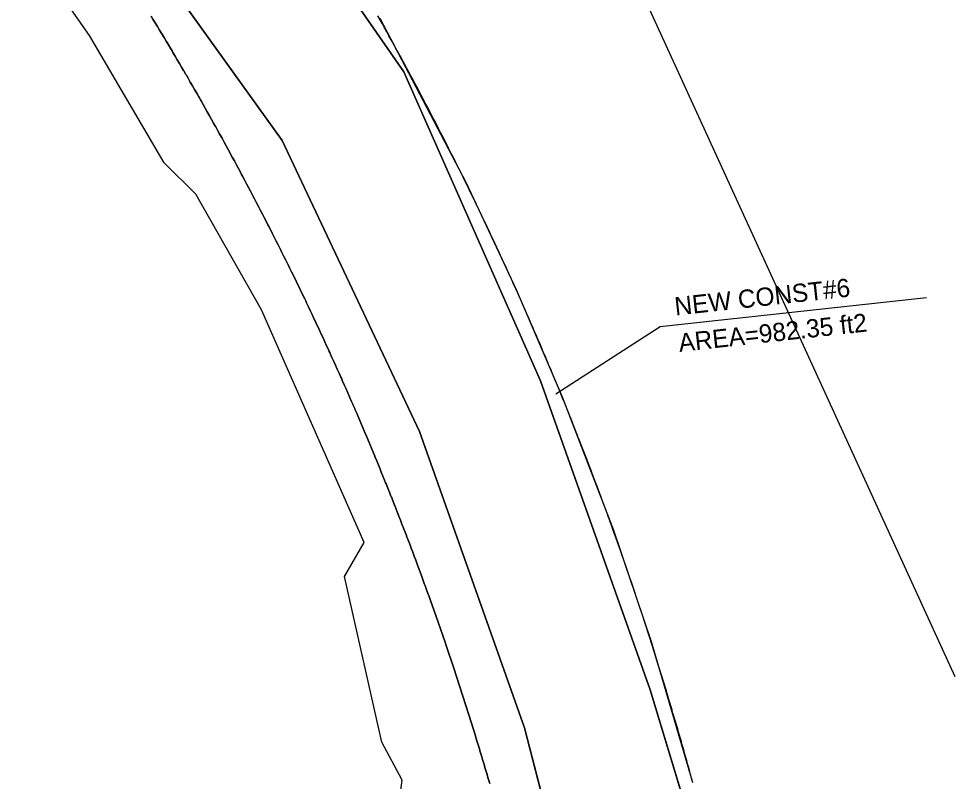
# Model space of a CAD drawing. Extents: x 1509538 to 1510847, y 401283 to 402022.
# Drawn here: x 1509686.3 to 1509828.9, y 401749.8 to 401866.7 of the extents above; entities that cross this region are included whole.
import ezdxf

# ---------------------------------------------------------------- set-up
doc = ezdxf.new("R2010")
doc.units = 0
for name, color, linetype in [('LAWE_P_T', 7, 'Continuous'), ('Level 2', 7, 'Continuous'), ('Level 24', 7, 'Continuous'), ('Level 3', 7, 'Continuous'), ('Level 5', 7, 'Continuous'), ('Level 8', 7, 'Continuous')]:
    doc.layers.add(name, color=color, linetype=linetype)

msp = doc.modelspace()

# ---------------------------------------------------------------- linework, layer by layer
at = {"layer": 'LAWE_P_T'}
msp.add_lwpolyline([(1509768.62, 401809.17), (1509784.6, 401819.5), (1509825.43, 401823.96)], dxfattribs=at)
at = {"layer": 'Level 2'}
for p, q in [((1509745.32, 401858.52), (1509715.31, 401901.72)), ((1509747.74, 401803.4), (1509763.81, 401758.01)), ((1509763.81, 401758.01), (1509775.46, 401713.07))]:
    msp.add_line(p, q, dxfattribs=at)
for points in [[(1509797.62, 401715.81), (1509783.05, 401763.87), (1509766.29, 401811.16), (1509745.32, 401858.52), (1509715.31, 401901.72)], [(1509690.27, 401895.46), (1509701.64, 401882.87), (1509726.68, 401848.01), (1509747.74, 401803.4), (1509763.81, 401758.01), (1509775.46, 401713.07), (1509786.05, 401661.7), (1509787.8, 401644.85), (1509788.16, 401621.99), (1509786.62, 401596.26), (1509780.1, 401566.45), (1509768.35, 401517.81), (1509766.66, 401509.48)], [(1509690.27, 401895.46), (1509701.64, 401882.87), (1509726.68, 401848.01), (1509747.74, 401803.4)], [(1509796.06, 401720.96), (1509783.05, 401763.87), (1509766.29, 401811.16), (1509745.32, 401858.52)]]:
    msp.add_lwpolyline(points, dxfattribs=at)
at = {"layer": 'Level 24'}
for points in [[(1509741.2, 401959.3), (1509785.47, 401862.6), (1509829.75, 401765.91)], [(1509754.99, 401675.99), (1509750.34, 401698.83), (1509743.92, 401723.63), (1509740.85, 401734.45), (1509744.77, 401747.73), (1509745.08, 401750.04), (1509741.96, 401755.84), (1509736.22, 401781.21), (1509739.22, 401786.4), (1509723.5, 401822.07), (1509713.45, 401839.79), (1509708.57, 401844.58), (1509697.15, 401864.06), (1509686.29, 401879.63)]]:
    msp.add_lwpolyline(points, dxfattribs=at)
at = {"layer": 'Level 3'}
for points in [[(1509715.31, 401901.72), (1509745.32, 401858.52), (1509766.29, 401811.16), (1509783.05, 401763.87), (1509797.62, 401715.81)], [(1509747.74, 401803.4), (1509726.68, 401848.01), (1509701.64, 401882.87), (1509690.27, 401895.46)], [(1509706.59, 401867.05), (1509706.88, 401866.57), (1509707.22, 401866.01), (1509707.56, 401865.44), (1509707.56, 401865.44), (1509707.9, 401864.88), (1509708.24, 401864.31), (1509708.58, 401863.75), (1509708.92, 401863.18), (1509709.09, 401862.9), (1509709.26, 401862.62), (1509709.6, 401862.05), (1509709.8, 401861.71), (1509709.93, 401861.49), (1509710.27, 401860.92), (1509710.6, 401860.35), (1509710.94, 401859.78), (1509711.27, 401859.22), (1509711.56, 401858.72), (1509711.6, 401858.65), (1509711.94, 401858.08), (1509712, 401857.97), (1509712.27, 401857.51), (1509712.6, 401856.94), (1509712.93, 401856.36), (1509713.26, 401855.79), (1509713.58, 401855.22), (1509713.91, 401854.65), (1509713.99, 401854.52), (1509714.17, 401854.2), (1509714.24, 401854.08), (1509714.56, 401853.51), (1509714.89, 401852.93), (1509715.21, 401852.36), (1509715.54, 401851.78), (1509715.86, 401851.21), (1509716.18, 401850.63), (1509716.3, 401850.41), (1509716.37, 401850.3), (1509716.5, 401850.06), (1509716.82, 401849.48), (1509717.14, 401848.91), (1509717.46, 401848.33), (1509717.78, 401847.75), (1509718.09, 401847.17), (1509718.4, 401846.61), (1509718.41, 401846.59), (1509718.71, 401846.05), (1509718.73, 401846.02), (1509719.04, 401845.44), (1509719.36, 401844.86), (1509719.67, 401844.28), (1509719.98, 401843.7), (1509720.29, 401843.12), (1509720.47, 401842.79), (1509720.6, 401842.53), (1509720.91, 401841.95), (1509721.01, 401841.78), (1509721.22, 401841.37), (1509721.53, 401840.79), (1509721.84, 401840.21), (1509722.15, 401839.62), (1509722.45, 401839.04), (1509722.5, 401838.95), (1509722.76, 401838.45), (1509723.06, 401837.87), (1509723.26, 401837.48), (1509723.36, 401837.28), (1509723.67, 401836.7), (1509723.97, 401836.11), (1509724.27, 401835.53), (1509724.5, 401835.09), (1509724.57, 401834.94), (1509724.87, 401834.35), (1509725.17, 401833.77), (1509725.47, 401833.18), (1509725.47, 401833.17), (1509725.77, 401832.59), (1509726.06, 401832), (1509726.36, 401831.41), (1509726.46, 401831.21), (1509726.65, 401830.82), (1509726.95, 401830.23), (1509727.24, 401829.64), (1509727.53, 401829.05), (1509727.64, 401828.83), (1509727.82, 401828.46), (1509728.11, 401827.87), (1509728.39, 401827.32), (1509728.4, 401827.28), (1509728.7, 401826.69), (1509728.98, 401826.09), (1509729.27, 401825.5), (1509729.56, 401824.91), (1509729.77, 401824.47), (1509729.84, 401824.31), (1509730.13, 401823.72), (1509730.28, 401823.41), (1509730.41, 401823.12), (1509730.7, 401822.53), (1509730.98, 401821.93), (1509731.26, 401821.34), (1509731.54, 401820.74), (1509731.82, 401820.15), (1509731.85, 401820.09), (1509732.1, 401819.55), (1509732.14, 401819.48), (1509732.38, 401818.95), (1509732.66, 401818.35), (1509732.94, 401817.76), (1509733.21, 401817.16), (1509733.49, 401816.56), (1509733.76, 401815.96), (1509733.89, 401815.69), (1509733.96, 401815.53), (1509734.04, 401815.36), (1509734.31, 401814.76), (1509734.58, 401814.16), (1509734.85, 401813.56), (1509735.12, 401812.96), (1509735.39, 401812.36), (1509735.66, 401811.76), (1509735.75, 401811.57), (1509735.88, 401811.27), (1509735.93, 401811.15), (1509736.2, 401810.55), (1509736.47, 401809.95), (1509736.73, 401809.34), (1509737, 401808.74), (1509737.26, 401808.14), (1509737.5, 401807.59), (1509737.52, 401807.53), (1509737.79, 401806.93), (1509737.83, 401806.83), (1509738.05, 401806.32), (1509738.31, 401805.72), (1509738.57, 401805.11), (1509738.83, 401804.51), (1509739.08, 401803.9), (1509739.21, 401803.6), (1509739.34, 401803.29), (1509739.6, 401802.69), (1509739.74, 401802.36), (1509739.85, 401802.08), (1509740.11, 401801.47), (1509740.36, 401800.86), (1509740.62, 401800.26), (1509740.87, 401799.65), (1509740.89, 401799.59), (1509741.12, 401799.04), (1509741.37, 401798.43), (1509741.59, 401797.89), (1509741.62, 401797.82), (1509741.87, 401797.21), (1509742.12, 401796.6), (1509742.37, 401795.99), (1509742.53, 401795.57), (1509742.61, 401795.38), (1509742.86, 401794.76), (1509743.11, 401794.15), (1509743.35, 401793.54), (1509743.41, 401793.39), (1509743.59, 401792.93), (1509743.84, 401792.31), (1509744.08, 401791.7), (1509744.14, 401791.53), (1509744.32, 401791.09), (1509744.56, 401790.47), (1509744.8, 401789.86), (1509745.04, 401789.24), (1509745.18, 401788.87), (1509745.27, 401788.63), (1509745.51, 401788.02), (1509745.71, 401787.48), (1509745.75, 401787.4), (1509745.98, 401786.78), (1509746.22, 401786.17), (1509746.45, 401785.55), (1509746.68, 401784.93), (1509746.91, 401784.34), (1509746.91, 401784.32), (1509747.14, 401783.7), (1509747.25, 401783.42), (1509747.37, 401783.08), (1509747.6, 401782.46), (1509747.83, 401781.85), (1509748.06, 401781.23), (1509748.29, 401780.61), (1509748.51, 401779.99), (1509748.58, 401779.79), (1509748.74, 401779.37), (1509748.75, 401779.34), (1509748.96, 401778.75), (1509749.18, 401778.13), (1509749.41, 401777.51), (1509750.21, 401775.25), (1509750.22, 401775.22), (1509751.64, 401771.14), (1509751.81, 401770.64), (1509753.02, 401767.03), (1509753.35, 401766.04), (1509754.37, 401762.9), (1509754.84, 401761.43), (1509755.69, 401758.75), (1509756.29, 401756.8), (1509756.43, 401756.35), (1509756.57, 401755.89), (1509756.71, 401755.43), (1509756.85, 401754.98), (1509756.97, 401754.6), (1509756.99, 401754.52), (1509757.13, 401754.07), (1509757.26, 401753.61), (1509757.4, 401753.16), (1509757.54, 401752.7), (1509757.67, 401752.24), (1509757.7, 401752.16), (1509757.81, 401751.79), (1509757.94, 401751.33), (1509758.08, 401750.87), (1509758.21, 401750.44), (1509758.21, 401750.42), (1509758.34, 401749.96), (1509758.48, 401749.5)], [(1509789.62, 401749.6), (1509789.51, 401749.99), (1509789.48, 401750.09), (1509789.35, 401750.58), (1509789.29, 401750.79), (1509789.22, 401751.06), (1509789.08, 401751.55), (1509788.95, 401752.04), (1509788.81, 401752.53), (1509788.67, 401753.01), (1509788.54, 401753.5), (1509788.4, 401753.99), (1509788.27, 401754.43), (1509788.26, 401754.47), (1509788.12, 401754.96), (1509787.99, 401755.45), (1509787.9, 401755.75), (1509787.85, 401755.93), (1509787.71, 401756.42), (1509787.57, 401756.9), (1509787.43, 401757.39), (1509787.29, 401757.88), (1509787.15, 401758.36), (1509787, 401758.85), (1509787, 401758.87), (1509786.86, 401759.33), (1509786.72, 401759.82), (1509786.57, 401760.3), (1509786.46, 401760.7), (1509786.43, 401760.79), (1509786.29, 401761.27), (1509786.14, 401761.76), (1509786, 401762.24), (1509785.85, 401762.72), (1509785.71, 401763.21), (1509785.68, 401763.29), (1509785.56, 401763.69), (1509785.41, 401764.18), (1509785.26, 401764.66), (1509785.11, 401765.14), (1509784.97, 401765.63), (1509784.32, 401767.7), (1509783.43, 401770.54), (1509782.93, 401772.1), (1509781.84, 401775.44), (1509781.49, 401776.48), (1509780.2, 401780.32), (1509780.02, 401780.85), (1509778.51, 401785.19), (1509778.51, 401785.21), (1509777.65, 401787.61), (1509777.42, 401788.27), (1509777.18, 401788.93), (1509776.95, 401789.56), (1509776.94, 401789.59), (1509776.78, 401790.04), (1509776.7, 401790.25), (1509776.46, 401790.91), (1509776.22, 401791.56), (1509775.98, 401792.22), (1509775.74, 401792.88), (1509775.5, 401793.53), (1509775.36, 401793.89), (1509775.25, 401794.19), (1509775.01, 401794.84), (1509775, 401794.87), (1509774.76, 401795.5), (1509774.51, 401796.15), (1509774.26, 401796.81), (1509774.02, 401797.46), (1509773.77, 401798.12), (1509773.73, 401798.21), (1509773.52, 401798.77), (1509773.26, 401799.42), (1509773.17, 401799.68), (1509773.01, 401800.08), (1509772.76, 401800.73), (1509772.5, 401801.38), (1509772.25, 401802.03), (1509772.06, 401802.51), (1509772, 401802.68), (1509771.74, 401803.34), (1509771.48, 401803.99), (1509771.28, 401804.48), (1509771.22, 401804.64), (1509770.96, 401805.29), (1509770.7, 401805.94), (1509770.44, 401806.59), (1509770.36, 401806.79), (1509770.18, 401807.23), (1509769.92, 401807.88), (1509769.65, 401808.53), (1509769.39, 401809.18), (1509769.36, 401809.25), (1509769.12, 401809.83), (1509768.86, 401810.47), (1509768.61, 401811.07), (1509768.59, 401811.12), (1509768.32, 401811.77), (1509768.05, 401812.41), (1509767.78, 401813.06), (1509767.51, 401813.7), (1509767.38, 401814.01), (1509767.24, 401814.35), (1509766.97, 401814.99), (1509766.83, 401815.32), (1509766.69, 401815.64), (1509766.42, 401816.28), (1509766.14, 401816.93), (1509765.87, 401817.57), (1509765.59, 401818.21), (1509765.36, 401818.74), (1509765.31, 401818.85), (1509765.03, 401819.5), (1509765.01, 401819.56), (1509764.75, 401820.14), (1509764.47, 401820.78), (1509764.19, 401821.42), (1509763.91, 401822.06), (1509763.63, 401822.7), (1509763.34, 401823.34), (1509763.29, 401823.46), (1509763.15, 401823.78), (1509763.06, 401823.98), (1509762.77, 401824.62), (1509762.49, 401825.26), (1509762.2, 401825.9), (1509761.91, 401826.53), (1509761.62, 401827.17), (1509761.33, 401827.81), (1509761.25, 401827.99), (1509761.17, 401828.16), (1509761.04, 401828.44), (1509760.75, 401829.08), (1509760.46, 401829.72), (1509760.16, 401830.35), (1509759.87, 401830.99), (1509759.57, 401831.62), (1509759.31, 401832.18), (1509759.28, 401832.26), (1509759.01, 401832.83), (1509758.98, 401832.89), (1509758.68, 401833.52), (1509758.39, 401834.16), (1509758.09, 401834.79), (1509757.79, 401835.42), (1509757.48, 401836.05), (1509757.34, 401836.35), (1509757.18, 401836.68), (1509756.88, 401837.31), (1509756.8, 401837.48), (1509756.58, 401837.94), (1509756.27, 401838.57), (1509755.97, 401839.21), (1509755.66, 401839.83), (1509755.35, 401840.46), (1509755.33, 401840.5), (1509755.04, 401841.09), (1509754.74, 401841.72), (1509754.54, 401842.11), (1509754.43, 401842.35), (1509754.12, 401842.97), (1509753.8, 401843.6), (1509753.49, 401844.23), (1509753.29, 401844.64), (1509753.18, 401844.85), (1509752.86, 401845.48), (1509752.55, 401846.1), (1509752.24, 401846.72), (1509752.23, 401846.73), (1509751.92, 401847.35), (1509751.6, 401847.98), (1509751.28, 401848.6), (1509751.2, 401848.76), (1509750.96, 401849.22), (1509750.64, 401849.84), (1509750.32, 401850.47), (1509750, 401851.09), (1509749.89, 401851.3), (1509749.68, 401851.71), (1509749.35, 401852.33), (1509749.08, 401852.85), (1509749.03, 401852.95), (1509748.71, 401853.57), (1509748.38, 401854.19), (1509748.05, 401854.81), (1509747.73, 401855.43), (1509747.5, 401855.86), (1509747.4, 401856.05), (1509747.07, 401856.66), (1509746.93, 401856.93), (1509746.74, 401857.28), (1509746.41, 401857.9), (1509746.08, 401858.51), (1509745.74, 401859.13), (1509745.41, 401859.74), (1509745.08, 401860.36), (1509745.06, 401860.39), (1509744.74, 401860.97), (1509744.73, 401860.99), (1509744.41, 401861.59), (1509744.07, 401862.2), (1509743.73, 401862.82), (1509743.39, 401863.43), (1509743.05, 401864.04), (1509742.71, 401864.65), (1509742.57, 401864.91), (1509742.5, 401865.03), (1509742.37, 401865.26), (1509742.03, 401865.87), (1509741.69, 401866.48), (1509741.34, 401867.09)], [(1509775.46, 401713.07), (1509763.81, 401758.01), (1509747.74, 401803.4)]]:
    msp.add_lwpolyline(points, dxfattribs=at)
at = {"layer": 'Level 5'}
for p, q in [((1509754.95, 401841.45), (1509741.72, 401866.65)), ((1509762.58, 401825.13), (1509754.95, 401841.45)), ((1509769.63, 401808.68), (1509762.58, 401825.13)), ((1509777.48, 401788.28), (1509769.63, 401808.68)), ((1509783.26, 401771.22), (1509777.48, 401788.28)), ((1509789.58, 401749.83), (1509783.26, 401771.22))]:
    msp.add_line(p, q, dxfattribs=at)
for points in [[(1509758.48, 401749.5), (1509758.34, 401749.96), (1509758.21, 401750.42), (1509758.21, 401750.44), (1509758.08, 401750.87), (1509757.94, 401751.33), (1509757.81, 401751.79), (1509757.7, 401752.16), (1509757.67, 401752.24), (1509757.54, 401752.7), (1509757.4, 401753.16), (1509757.26, 401753.61), (1509757.13, 401754.07), (1509756.99, 401754.52), (1509756.97, 401754.6), (1509756.85, 401754.98), (1509756.71, 401755.43), (1509756.57, 401755.89), (1509756.43, 401756.35), (1509756.29, 401756.8), (1509755.69, 401758.75), (1509754.84, 401761.43), (1509754.37, 401762.9), (1509753.35, 401766.04), (1509753.02, 401767.03), (1509751.81, 401770.64), (1509751.64, 401771.14), (1509750.22, 401775.22), (1509750.21, 401775.25), (1509749.41, 401777.51), (1509749.18, 401778.13), (1509748.96, 401778.75), (1509748.75, 401779.34), (1509748.74, 401779.37), (1509748.58, 401779.79), (1509748.51, 401779.99), (1509748.29, 401780.61), (1509748.06, 401781.23), (1509747.83, 401781.85), (1509747.6, 401782.46), (1509747.37, 401783.08), (1509747.25, 401783.42), (1509747.14, 401783.7), (1509746.91, 401784.32), (1509746.91, 401784.34), (1509746.68, 401784.93), (1509746.45, 401785.55), (1509746.22, 401786.17), (1509745.98, 401786.78), (1509745.75, 401787.4), (1509745.71, 401787.48), (1509745.51, 401788.02), (1509745.27, 401788.63), (1509745.18, 401788.87), (1509745.04, 401789.24), (1509744.8, 401789.86), (1509744.56, 401790.47), (1509744.32, 401791.09), (1509744.14, 401791.53), (1509744.08, 401791.7), (1509743.84, 401792.31), (1509743.59, 401792.93), (1509743.41, 401793.39), (1509743.35, 401793.54), (1509743.11, 401794.15), (1509742.86, 401794.76), (1509742.61, 401795.38), (1509742.53, 401795.57), (1509742.37, 401795.99), (1509742.12, 401796.6), (1509741.87, 401797.21), (1509741.62, 401797.82), (1509741.59, 401797.89), (1509741.37, 401798.43), (1509741.12, 401799.04), (1509740.89, 401799.59), (1509740.87, 401799.65), (1509740.62, 401800.26), (1509740.36, 401800.86), (1509740.11, 401801.47), (1509739.85, 401802.08), (1509739.74, 401802.36), (1509739.6, 401802.69), (1509739.34, 401803.29), (1509739.21, 401803.6), (1509739.08, 401803.9), (1509738.83, 401804.51), (1509738.57, 401805.11), (1509738.31, 401805.72), (1509738.05, 401806.32), (1509737.83, 401806.83), (1509737.79, 401806.93), (1509737.52, 401807.53), (1509737.5, 401807.59), (1509737.26, 401808.14), (1509737, 401808.74), (1509736.73, 401809.34), (1509736.47, 401809.95), (1509736.2, 401810.55), (1509735.93, 401811.15), (1509735.88, 401811.27), (1509735.75, 401811.57), (1509735.66, 401811.76), (1509735.39, 401812.36), (1509735.12, 401812.96), (1509734.85, 401813.56), (1509734.58, 401814.16), (1509734.31, 401814.76), (1509734.04, 401815.36), (1509733.96, 401815.53), (1509733.89, 401815.69), (1509733.76, 401815.96), (1509733.49, 401816.56), (1509733.21, 401817.16), (1509732.94, 401817.76), (1509732.66, 401818.35), (1509732.38, 401818.95), (1509732.14, 401819.48), (1509732.1, 401819.55), (1509731.85, 401820.09), (1509731.82, 401820.15), (1509731.54, 401820.74), (1509731.26, 401821.34), (1509730.98, 401821.93), (1509730.7, 401822.53), (1509730.41, 401823.12), (1509730.28, 401823.41), (1509730.13, 401823.72), (1509729.84, 401824.31), (1509729.77, 401824.47), (1509729.56, 401824.91), (1509729.27, 401825.5), (1509728.98, 401826.09), (1509728.7, 401826.69), (1509728.4, 401827.28), (1509728.39, 401827.32), (1509728.11, 401827.87), (1509727.82, 401828.46), (1509727.64, 401828.83), (1509727.53, 401829.05), (1509727.24, 401829.64), (1509726.95, 401830.23), (1509726.65, 401830.82), (1509726.46, 401831.21), (1509726.36, 401831.41), (1509726.06, 401832), (1509725.77, 401832.59), (1509725.47, 401833.17), (1509725.47, 401833.18), (1509725.17, 401833.77), (1509724.87, 401834.35), (1509724.57, 401834.94), (1509724.5, 401835.09), (1509724.27, 401835.53), (1509723.97, 401836.11), (1509723.67, 401836.7), (1509723.36, 401837.28), (1509723.26, 401837.48), (1509723.06, 401837.87), (1509722.76, 401838.45), (1509722.5, 401838.95), (1509722.45, 401839.04), (1509722.15, 401839.62), (1509721.84, 401840.21), (1509721.53, 401840.79), (1509721.22, 401841.37), (1509721.01, 401841.78), (1509720.91, 401841.95), (1509720.6, 401842.53), (1509720.47, 401842.79), (1509720.29, 401843.12), (1509719.98, 401843.7), (1509719.67, 401844.28), (1509719.36, 401844.86), (1509719.04, 401845.44), (1509718.73, 401846.02), (1509718.71, 401846.05), (1509718.41, 401846.59), (1509718.4, 401846.61), (1509718.09, 401847.17), (1509717.78, 401847.75), (1509717.46, 401848.33), (1509717.14, 401848.91), (1509716.82, 401849.48), (1509716.5, 401850.06), (1509716.37, 401850.3), (1509716.3, 401850.41), (1509716.18, 401850.63), (1509715.86, 401851.21), (1509715.54, 401851.78), (1509715.21, 401852.36), (1509714.89, 401852.93), (1509714.56, 401853.51), (1509714.24, 401854.08), (1509714.17, 401854.2), (1509713.99, 401854.52), (1509713.91, 401854.65), (1509713.58, 401855.22), (1509713.26, 401855.79), (1509712.93, 401856.36), (1509712.6, 401856.94), (1509712.27, 401857.51), (1509712, 401857.97), (1509711.94, 401858.08), (1509711.6, 401858.65), (1509711.56, 401858.72), (1509711.27, 401859.22), (1509710.94, 401859.78), (1509710.6, 401860.35), (1509710.27, 401860.92), (1509709.93, 401861.49), (1509709.8, 401861.71), (1509709.6, 401862.05), (1509709.26, 401862.62), (1509709.09, 401862.9), (1509708.92, 401863.18), (1509708.58, 401863.75), (1509708.24, 401864.31), (1509707.9, 401864.88), (1509707.56, 401865.44), (1509707.56, 401865.44), (1509707.22, 401866.01), (1509706.88, 401866.57), (1509706.59, 401867.05)], [(1509706.59, 401867.05), (1509706.88, 401866.57), (1509707.22, 401866.01), (1509707.56, 401865.44), (1509707.56, 401865.44), (1509707.9, 401864.88), (1509708.24, 401864.31), (1509708.58, 401863.75), (1509708.92, 401863.18), (1509709.09, 401862.9), (1509709.26, 401862.62), (1509709.6, 401862.05), (1509709.8, 401861.71), (1509709.93, 401861.49), (1509710.27, 401860.92), (1509710.6, 401860.35), (1509710.94, 401859.78), (1509711.27, 401859.22), (1509711.56, 401858.72), (1509711.6, 401858.65), (1509711.94, 401858.08), (1509712, 401857.97), (1509712.27, 401857.51), (1509712.6, 401856.94), (1509712.93, 401856.36), (1509713.26, 401855.79), (1509713.58, 401855.22), (1509713.91, 401854.65), (1509713.99, 401854.52), (1509714.17, 401854.2), (1509714.24, 401854.08), (1509714.56, 401853.51), (1509714.89, 401852.93), (1509715.21, 401852.36), (1509715.54, 401851.78), (1509715.86, 401851.21), (1509716.18, 401850.63), (1509716.3, 401850.41), (1509716.37, 401850.3), (1509716.5, 401850.06), (1509716.82, 401849.48), (1509717.14, 401848.91), (1509717.46, 401848.33), (1509717.78, 401847.75), (1509718.09, 401847.17), (1509718.4, 401846.61), (1509718.41, 401846.59), (1509718.71, 401846.05), (1509718.73, 401846.02), (1509719.04, 401845.44), (1509719.36, 401844.86), (1509719.67, 401844.28), (1509719.98, 401843.7), (1509720.29, 401843.12), (1509720.47, 401842.79), (1509720.6, 401842.53), (1509720.91, 401841.95), (1509721.01, 401841.78), (1509721.22, 401841.37), (1509721.53, 401840.79), (1509721.84, 401840.21), (1509722.15, 401839.62), (1509722.45, 401839.04), (1509722.5, 401838.95), (1509722.76, 401838.45), (1509723.06, 401837.87), (1509723.26, 401837.48), (1509723.36, 401837.28), (1509723.67, 401836.7), (1509723.97, 401836.11), (1509724.27, 401835.53), (1509724.5, 401835.09), (1509724.57, 401834.94), (1509724.87, 401834.35), (1509725.17, 401833.77), (1509725.47, 401833.18), (1509725.47, 401833.17), (1509725.77, 401832.59), (1509726.06, 401832), (1509726.36, 401831.41), (1509726.46, 401831.21), (1509726.65, 401830.82), (1509726.95, 401830.23), (1509727.24, 401829.64), (1509727.53, 401829.05), (1509727.64, 401828.83), (1509727.82, 401828.46), (1509728.11, 401827.87), (1509728.39, 401827.32), (1509728.4, 401827.28), (1509728.7, 401826.69), (1509728.98, 401826.09), (1509729.27, 401825.5), (1509729.56, 401824.91), (1509729.77, 401824.47), (1509729.84, 401824.31), (1509730.13, 401823.72), (1509730.28, 401823.41), (1509730.41, 401823.12), (1509730.7, 401822.53), (1509730.98, 401821.93), (1509731.26, 401821.34), (1509731.54, 401820.74), (1509731.82, 401820.15), (1509731.85, 401820.09), (1509732.1, 401819.55), (1509732.14, 401819.48), (1509732.38, 401818.95), (1509732.66, 401818.35), (1509732.94, 401817.76), (1509733.21, 401817.16), (1509733.49, 401816.56), (1509733.76, 401815.96), (1509733.89, 401815.69), (1509733.96, 401815.53), (1509734.04, 401815.36), (1509734.31, 401814.76), (1509734.58, 401814.16), (1509734.85, 401813.56), (1509735.12, 401812.96), (1509735.39, 401812.36), (1509735.66, 401811.76), (1509735.75, 401811.57), (1509735.88, 401811.27), (1509735.93, 401811.15), (1509736.2, 401810.55), (1509736.47, 401809.95), (1509736.73, 401809.34), (1509737, 401808.74), (1509737.26, 401808.14), (1509737.5, 401807.59), (1509737.52, 401807.53), (1509737.79, 401806.93), (1509737.83, 401806.83), (1509738.05, 401806.32), (1509738.31, 401805.72), (1509738.57, 401805.11), (1509738.83, 401804.51), (1509739.08, 401803.9), (1509739.21, 401803.6), (1509739.34, 401803.29), (1509739.6, 401802.69), (1509739.74, 401802.36), (1509739.85, 401802.08), (1509740.11, 401801.47), (1509740.36, 401800.86), (1509740.62, 401800.26), (1509740.87, 401799.65), (1509740.89, 401799.59), (1509741.12, 401799.04), (1509741.37, 401798.43), (1509741.59, 401797.89), (1509741.62, 401797.82), (1509741.87, 401797.21), (1509742.12, 401796.6), (1509742.37, 401795.99), (1509742.53, 401795.57), (1509742.61, 401795.38), (1509742.86, 401794.76), (1509743.11, 401794.15), (1509743.35, 401793.54), (1509743.41, 401793.39), (1509743.59, 401792.93), (1509743.84, 401792.31), (1509744.08, 401791.7), (1509744.14, 401791.53), (1509744.32, 401791.09), (1509744.56, 401790.47), (1509744.8, 401789.86), (1509745.04, 401789.24), (1509745.18, 401788.87), (1509745.27, 401788.63), (1509745.51, 401788.02), (1509745.71, 401787.48), (1509745.75, 401787.4), (1509745.98, 401786.78), (1509746.22, 401786.17), (1509746.45, 401785.55), (1509746.68, 401784.93), (1509746.91, 401784.34), (1509746.91, 401784.32), (1509747.14, 401783.7), (1509747.25, 401783.42), (1509747.37, 401783.08), (1509747.6, 401782.46), (1509747.83, 401781.85), (1509748.06, 401781.23), (1509748.29, 401780.61), (1509748.51, 401779.99), (1509748.58, 401779.79), (1509748.74, 401779.37), (1509748.75, 401779.34), (1509748.96, 401778.75), (1509749.18, 401778.13), (1509749.41, 401777.51), (1509750.21, 401775.25), (1509750.22, 401775.22), (1509751.64, 401771.14), (1509751.81, 401770.64), (1509753.02, 401767.03), (1509753.35, 401766.04), (1509754.37, 401762.9), (1509754.84, 401761.43), (1509755.69, 401758.75), (1509756.29, 401756.8), (1509756.43, 401756.35), (1509756.57, 401755.89), (1509756.71, 401755.43), (1509756.85, 401754.98), (1509756.97, 401754.6), (1509756.99, 401754.52), (1509757.13, 401754.07), (1509757.26, 401753.61), (1509757.4, 401753.16), (1509757.54, 401752.7), (1509757.67, 401752.24), (1509757.7, 401752.16), (1509757.81, 401751.79), (1509757.94, 401751.33), (1509758.08, 401750.87), (1509758.21, 401750.44), (1509758.21, 401750.42), (1509758.34, 401749.96), (1509758.48, 401749.5)]]:
    msp.add_lwpolyline(points, dxfattribs=at)
at = {"layer": 'Level 8'}
for p, q in [((1509715.31, 401901.72), (1509745.32, 401858.52)), ((1509763.81, 401758.01), (1509747.74, 401803.4)), ((1509775.46, 401713.07), (1509763.81, 401758.01))]:
    msp.add_line(p, q, dxfattribs=at)
for points in [[(1509747.74, 401803.4), (1509726.68, 401848.01), (1509701.64, 401882.87), (1509690.27, 401895.46)], [(1509745.32, 401858.52), (1509766.29, 401811.16), (1509783.05, 401763.87), (1509796.06, 401720.96)]]:
    msp.add_lwpolyline(points, dxfattribs=at)

# ---------------------------------------------------------------- texts
at = {"layer": 'LAWE_P_T'}
for s, p in [('NEW CONST#6', (1509786.96, 401821.17)), ('AREA=982.35 ft2', (1509787.57, 401815.6))]:
    msp.add_text(s, height=2.8, rotation=6.2219, dxfattribs=at).set_placement(p)

doc.saveas('drawing.dxf')
